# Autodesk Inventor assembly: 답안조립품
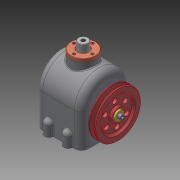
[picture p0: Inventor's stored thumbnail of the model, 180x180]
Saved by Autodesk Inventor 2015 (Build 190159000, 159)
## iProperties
Created: 2023-03
Part Number: 답안조립품
Document SubType Name: Assembly
Designer: home
Author: home
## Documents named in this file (22)
- C:\Users\home\Desktop\730306V1010\답안조립품.iam
- C:\Users\home\Desktop\730306V1010\E형 멈춤링 13 x 12.ipt
- C:\Users\home\Desktop\730306V1010\V-벨트풀리.ipt
- C:\Users\home\Desktop\730306V1010\고정핀.ipt
- C:\Users\home\Desktop\730306V1010\뒷커버.ipt
- C:\Users\home\Desktop\730306V1010\링크.ipt
- C:\Users\home\Desktop\730306V1010\멈춤링 25 x 1.2.ipt
- 멈춤링 25 x 1.2.ipt
- C:\Users\home\Desktop\730306V1010\베어링 6205.ipt
- 베어링 6205.ipt
- C:\Users\home\Desktop\730306V1010\본체.ipt
- C:\Users\home\Desktop\730306V1010\볼트 M4 x 12.ipt
- C:\Users\home\Desktop\730306V1010\볼트 M8 x 16.ipt
- C:\Users\home\Desktop\730306V1010\부시.ipt
- C:\Users\home\Desktop\730306V1010\슬라이더.ipt
- C:\Users\home\Desktop\730306V1010\앞커버.ipt
- C:\Users\home\Desktop\730306V1010\엔드캡.ipt
- C:\Users\home\Desktop\730306V1010\오일실 25 40 8.ipt
- 오일실 25 40 8.ipt
- C:\Users\home\Desktop\730306V1010\윗커버.ipt
- C:\Users\home\Desktop\730306V1010\키 6x6x14.ipt
- C:\Users\home\Desktop\730306V1010\편심축.ipt
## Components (3 placed, 3 different names)
1. E형 멈춤링 13 x 12:1
2. V-벨트풀리:1
3. 고정핀:1
